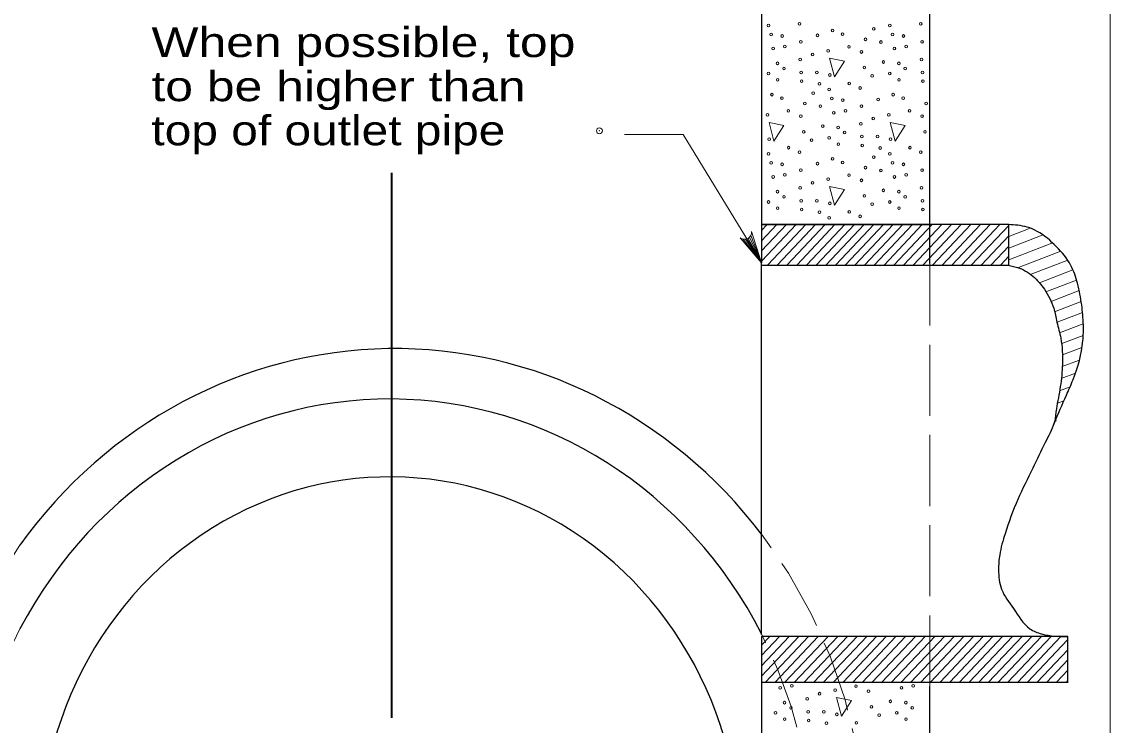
# Model space of a CAD drawing. Extents: x 1083.1 to 1117.1, y 697.4 to 719.4.
# Drawn here: x 1087.12 to 1092.81, y 703.92 to 707.6 of the extents above; entities that cross this region are included whole.
import ezdxf

# ---------------------------------------------------------------- set-up
doc = ezdxf.new("R2010")
doc.units = 0
doc.header["$LTSCALE"] = 0.062
doc.header["$PDMODE"] = 32
doc.header["$PDSIZE"] = 0.031
doc.linetypes.add('LONG_DASHED', pattern=[7.5, 6, -1.5])
doc.layers.add('1', color=7, linetype='Continuous', lineweight=13)

msp = doc.modelspace()

# ---------------------------------------------------------------- linework, layer by layer
at = {"layer": '1', "lineweight": 25}
for p, q in [((1090.98767, 710.498), (1090.98767, 706.54908)), ((1091.86725, 706.529), (1091.86725, 710.48442)), ((1090.98767, 706.54908), (1090.98767, 706.33992)), ((1090.98767, 706.5395), (1091.86867, 706.5395)), ((1091.86867, 706.5395), (1090.98767, 706.5395)), ((1091.86725, 706.33625), (1091.86725, 706.529)), ((1092.28083, 706.5395), (1091.86867, 706.5395)), ((1090.98767, 704.39392), (1090.98767, 706.33992)), ((1092.59017, 704.3835), (1090.987, 704.3835)), ((1090.98767, 704.3835), (1090.98767, 704.14825)), ((1092.59017, 704.14433), (1092.59017, 704.3835)), ((1090.98767, 704.14825), (1090.98767, 701.31858)), ((1090.98767, 704.14433), (1092.5915, 704.14433)), ((1091.86725, 700.32092), (1091.86725, 704.12275))]:
    msp.add_line(p, q, dxfattribs=at)
at = {"layer": '1'}
for p, q in [((1092.8115, 701.31858), (1092.8115, 707.72683)), ((1090.98767, 706.34775), (1091.16875, 706.5395)), ((1090.98767, 706.4015), (1091.118, 706.5395)), ((1090.98767, 706.45525), (1091.06725, 706.5395)), ((1090.98767, 706.50892), (1091.01642, 706.5395)), ((1091.02083, 706.32917), (1091.21942, 706.5395)), ((1091.07167, 706.32917), (1091.27017, 706.5395)), ((1091.12242, 706.32917), (1091.321, 706.5395)), ((1091.17308, 706.32917), (1091.37175, 706.5395)), ((1091.22383, 706.32917), (1091.4225, 706.5395)), ((1091.27458, 706.32917), (1091.47325, 706.5395)), ((1091.32542, 706.32917), (1091.524, 706.5395)), ((1091.37617, 706.32917), (1091.57475, 706.5395)), ((1091.42683, 706.32917), (1091.6255, 706.5395)), ((1091.47758, 706.32917), (1091.67625, 706.5395)), ((1091.52833, 706.32917), (1091.727, 706.5395)), ((1091.57917, 706.32917), (1091.77775, 706.5395)), ((1091.62992, 706.32917), (1091.8285, 706.5395)), ((1091.68067, 706.32917), (1091.87925, 706.5395)), ((1091.73133, 706.32917), (1091.93, 706.5395)), ((1091.78208, 706.32917), (1091.98075, 706.5395)), ((1091.83283, 706.32917), (1092.0315, 706.5395)), ((1091.88358, 706.32917), (1092.08225, 706.5395)), ((1091.93433, 706.32917), (1092.133, 706.5395)), ((1091.98508, 706.32917), (1092.18375, 706.5395)), ((1092.03583, 706.32917), (1092.2345, 706.5395)), ((1092.08658, 706.32917), (1092.28083, 706.53483)), ((1090.91675, 706.467), (1090.98767, 706.33992)), ((1090.92533, 706.47367), (1090.98767, 706.33992)), ((1090.93208, 706.48325), (1090.98767, 706.33992)), ((1092.13733, 706.32917), (1092.28083, 706.481)), ((1092.28083, 706.477), (1092.3935, 706.52042)), ((1092.28083, 706.41625), (1092.45508, 706.48342)), ((1090.892, 706.463), (1090.98767, 706.33992)), ((1090.9035, 706.46275), (1090.98767, 706.33992)), ((1092.18808, 706.32917), (1092.28083, 706.42733)), ((1092.28083, 706.35567), (1092.50575, 706.44233)), ((1092.23883, 706.32917), (1092.28083, 706.37358)), ((1092.33192, 706.31475), (1092.5525, 706.39975)), ((1092.39808, 706.27958), (1092.58942, 706.35325)), ((1092.44117, 706.2355), (1092.61575, 706.30283)), ((1092.47492, 706.18783), (1092.635, 706.2495)), ((1092.50283, 706.138), (1092.64875, 706.19408)), ((1092.52008, 706.08392), (1092.65925, 706.13758)), ((1092.53317, 706.02833), (1092.66642, 706.07967)), ((1092.54625, 705.97267), (1092.67058, 706.02067)), ((1092.55775, 705.9165), (1092.6705, 705.96)), ((1092.56208, 705.8575), (1092.66317, 705.89642)), ((1092.56058, 705.79633), (1092.64542, 705.829)), ((1092.55558, 705.73383), (1092.62975, 705.76233)), ((1092.54658, 705.66958), (1092.59625, 705.68883)), ((1092.53517, 705.6045), (1092.56842, 705.61742)), ((1092.52683, 705.51042), (1092.53092, 705.512)), ((1090.98767, 704.17658), (1091.183, 704.3835)), ((1090.98767, 704.23033), (1091.13233, 704.3835)), ((1090.98767, 704.28408), (1091.08158, 704.3835)), ((1090.98767, 704.33783), (1091.03083, 704.3835)), ((1091.00783, 704.14433), (1091.23383, 704.3835)), ((1091.05858, 704.14433), (1091.28458, 704.3835)), ((1091.10942, 704.14433), (1091.33533, 704.3835)), ((1091.16017, 704.14433), (1091.38608, 704.3835)), ((1091.21083, 704.14433), (1091.43683, 704.3835)), ((1091.26158, 704.14433), (1091.48758, 704.3835)), ((1091.31242, 704.14433), (1091.53833, 704.3835)), ((1091.36317, 704.14433), (1091.58908, 704.3835)), ((1091.41392, 704.14433), (1091.63983, 704.3835)), ((1091.46458, 704.14433), (1091.69058, 704.3835)), ((1091.51533, 704.14433), (1091.74133, 704.3835)), ((1091.56617, 704.14433), (1091.79208, 704.3835)), ((1091.61692, 704.14433), (1091.84275, 704.3835)), ((1091.66767, 704.14433), (1091.8935, 704.3835)), ((1091.71842, 704.14433), (1091.94425, 704.3835)), ((1091.76917, 704.14433), (1091.99508, 704.3835)), ((1091.81992, 704.14433), (1092.04583, 704.3835)), ((1091.87067, 704.14433), (1092.09658, 704.3835)), ((1091.9215, 704.14433), (1092.14725, 704.3835)), ((1091.97217, 704.14433), (1092.19808, 704.3835)), ((1092.02292, 704.14433), (1092.24883, 704.3835)), ((1092.07367, 704.14433), (1092.29958, 704.3835)), ((1092.12442, 704.14433), (1092.35033, 704.3835)), ((1092.17517, 704.14433), (1092.401, 704.3835)), ((1092.22592, 704.14433), (1092.45183, 704.3835)), ((1092.27667, 704.14433), (1092.50258, 704.3835)), ((1092.32742, 704.14433), (1092.55333, 704.3835)), ((1092.37817, 704.14433), (1092.59017, 704.36875)), ((1092.42892, 704.14433), (1092.59017, 704.315)), ((1092.47967, 704.14433), (1092.59017, 704.26133)), ((1092.53042, 704.14433), (1092.59017, 704.20758)), ((1092.58125, 704.14433), (1092.59017, 704.15375))]:
    msp.add_line(p, q, dxfattribs=at)
at = {"layer": '1', "lineweight": 35}
msp.add_line((1089.05217, 706.81108), (1089.05217, 703.95792), dxfattribs=at)
at = {"layer": '1', "linetype": 'LONG_DASHED'}
msp.add_line((1091.86725, 704.12275), (1091.86725, 706.33625), dxfattribs=at)
at = {"layer": '1'}
for points in [[(1091.34375, 707.40975), (1091.36942, 707.31242), (1091.42158, 707.39458)], [(1091.02658, 707.07392), (1091.05217, 706.97667), (1091.10442, 707.05883)], [(1091.66092, 707.07392), (1091.68658, 706.97667), (1091.73883, 707.05883)], [(1091.34375, 706.73817), (1091.36942, 706.64075), (1091.42158, 706.72292)], [(1091.38042, 704.06417), (1091.40608, 703.96683), (1091.45825, 704.049)]]:
    msp.add_lwpolyline(points, close=True, dxfattribs=at)
for points in [[(1090.98767, 706.33992), (1090.577, 707.011), (1090.27142, 707.011)], [(1090.87633, 706.47042), (1090.98767, 706.33992), (1090.93508, 706.50317)]]:
    msp.add_lwpolyline(points, dxfattribs=at)
at = {"layer": '1', "lineweight": 25}
msp.add_lwpolyline([(1090.98767, 706.32642), (1092.28083, 706.32642), (1092.28083, 706.5395)], dxfattribs=at)
at = {"layer": '1'}
msp.add_arc((1090.89909, 706.49869), 0.03631, 231.25375, 7.07988, dxfattribs=at)
for centre in [(1091.02402, 707.582), (1091.18589, 707.59017), (1091.35925, 707.55541), (1091.57447, 707.56387), (1091.65842, 707.582), (1091.8203, 707.59017), (1091.03776, 707.53487), (1091.09512, 707.52664), (1091.19277, 707.4958), (1091.28042, 707.53006), (1091.41148, 707.53638), (1091.53138, 707.50918), (1091.61216, 707.49497), (1091.67216, 707.53487), (1091.72952, 707.52664), (1091.82717, 707.4958), (1091.04797, 707.46049), (1091.10966, 707.4714), (1091.25467, 707.43026), (1091.33609, 707.44929), (1091.44484, 707.47017), (1091.50997, 707.44297), (1091.68237, 707.46049), (1091.74406, 707.4714), (1091.07117, 707.38342), (1091.18965, 707.40306), (1091.62474, 707.39041), (1091.70558, 707.38342), (1091.82405, 707.40306), (1091.02375, 707.32963), (1091.10485, 707.35683), (1091.19478, 707.33595), (1091.27704, 707.33595), (1091.34465, 707.32235), (1091.52541, 707.36136), (1091.56654, 707.31782), (1091.65815, 707.32963), (1091.73925, 707.35683), (1091.82918, 707.33595), (1091.07202, 707.29666), (1091.19731, 707.28972), (1091.29073, 707.27612), (1091.44658, 707.27791), (1091.70642, 707.29666), (1091.83172, 707.28972), (1091.04204, 707.21959), (1091.09428, 707.20056), (1091.25727, 707.22804), (1091.34122, 707.24618), (1091.35496, 707.19905), (1091.5031, 707.25435), (1091.67645, 707.21959), (1091.72868, 707.20056), (1091.21418, 707.17336), (1091.29496, 707.15914), (1091.41232, 707.19082), (1091.50997, 707.15998), (1091.59762, 707.19423), (1091.84858, 707.17336), (1091.01889, 707.11347), (1091.12764, 707.13435), (1091.19277, 707.10714), (1091.36517, 707.12466), (1091.42686, 707.13558), (1091.57188, 707.09444), (1091.65329, 707.11347), (1091.76204, 707.13435), (1091.82717, 707.10714), (1091.30754, 707.05459), (1091.38837, 707.04759), (1091.50685, 707.06724), (1091.02745, 706.98653), (1091.2082, 707.02554), (1091.24934, 706.98199), (1091.34095, 706.9938), (1091.42205, 707.021), (1091.51198, 707.00013), (1091.59424, 707.00013), (1091.66186, 706.98653), (1091.84261, 707.02554), (1091.12938, 706.94209), (1091.18589, 706.91852), (1091.38922, 706.96084), (1091.51452, 706.9539), (1091.60793, 706.9403), (1091.76378, 706.94209), (1091.8203, 706.91852), (1091.02402, 706.91035), (1091.03776, 706.86322), (1091.28042, 706.85841), (1091.35925, 706.88376), (1091.41148, 706.86473), (1091.57447, 706.89222), (1091.65842, 706.91035), (1091.67216, 706.86322), (1091.09512, 706.855), (1091.19277, 706.82416), (1091.53138, 706.83753), (1091.61216, 706.82332), (1091.72952, 706.855), (1091.82717, 706.82416), (1091.04797, 706.78884), (1091.10966, 706.79975), (1091.25467, 706.75861), (1091.33609, 706.77764), (1091.44484, 706.79852), (1091.50997, 706.77132), (1091.68237, 706.78884), (1091.74406, 706.79975), (1091.07117, 706.71177), (1091.18965, 706.73141), (1091.52541, 706.68971), (1091.62474, 706.71876), (1091.70558, 706.71177), (1091.82405, 706.73141), (1091.02375, 706.65798), (1091.10485, 706.68518), (1091.19478, 706.6643), (1091.27704, 706.6643), (1091.34465, 706.6507), (1091.56654, 706.64617), (1091.65815, 706.65798), (1091.73925, 706.68518), (1091.82918, 706.6643), (1091.07202, 706.62501), (1091.19731, 706.61807), (1091.29073, 706.60447), (1091.34122, 706.57453), (1091.44658, 706.60626), (1091.5031, 706.5827), (1091.70642, 706.62501), (1091.83172, 706.61807), (1091.14631, 704.12581), (1091.48148, 704.12458), (1091.78071, 704.12581), (1091.08461, 704.11489), (1091.29132, 704.08467), (1091.37274, 704.1037), (1091.54662, 704.09737), (1091.71902, 704.11489), (1091.10782, 704.03782), (1091.1415, 704.01124), (1091.2263, 704.05747), (1091.56205, 704.01577), (1091.66139, 704.04482), (1091.74222, 704.03782), (1091.7759, 704.01124), (1091.0604, 703.98403), (1091.23142, 703.99036), (1091.31369, 703.99036), (1091.3813, 703.97676), (1091.60318, 703.97222), (1091.6948, 703.98403), (1091.10867, 703.95107), (1091.23396, 703.94413), (1091.32738, 703.93053), (1091.48323, 703.93232), (1091.74307, 703.95107)]:
    msp.add_ellipse(centre, major_axis=(0, 0.00718), ratio=0.944544, dxfattribs=at)
at = {"layer": '1', "lineweight": 25}
for centre, major_axis, start_param, end_param in [((1089.06894, 703.28095), (0, -2.60983), 2.2495454, 4.0615652), ((1089.04094, 703.28499), (0, -2.34206), 2.0657148, 4.204739), ((1089.04277, 703.2802), (0, 1.93921), 4.5449685, 8.0045958)]:
    msp.add_ellipse(centre, major_axis=major_axis, ratio=0.944544, start_param=start_param, end_param=end_param, dxfattribs=at)
at = {"layer": '1', "linetype": 'LONG_DASHED'}
for centre, major_axis, start_param, end_param in [((1089.06894, 703.28095), (0, -2.60983), 4.0615652, 8.5327307), ((1089.04094, 703.28499), (0, -2.34206), 4.204739, 8.3489001)]:
    msp.add_ellipse(centre, major_axis=major_axis, ratio=0.944544, start_param=start_param, end_param=end_param, dxfattribs=at)
at = {"layer": '1', "lineweight": 25}
for points in [[(1092.5185, 705.501), (1092.582, 705.64633), (1092.61742, 705.72908), (1092.6685, 705.9315), (1092.67092, 706.01558), (1092.66225, 706.11942), (1092.64017, 706.23225), (1092.60583, 706.3255), (1092.53, 706.424), (1092.42975, 706.50408), (1092.37675, 706.5265), (1092.27958, 706.53967)], [(1092.27008, 706.32725), (1092.32625, 706.3155), (1092.407, 706.2695), (1092.46692, 706.20125), (1092.51592, 706.10158), (1092.533, 706.02917), (1092.55267, 705.94517), (1092.56142, 705.80983), (1092.55042, 705.69158), (1092.52975, 705.57458), (1092.5205, 705.50692)], [(1092.52058, 705.50708), (1092.5185, 705.501), (1092.47092, 705.3985), (1092.40633, 705.26442), (1092.32825, 705.1015), (1092.26117, 704.92133), (1092.23325, 704.81225), (1092.22717, 704.73342), (1092.24308, 704.631), (1092.30558, 704.52992), (1092.39117, 704.42475), (1092.45258, 704.39767), (1092.59017, 704.3835)]]:
    msp.add_spline(points, degree=3, dxfattribs=at)
at = {"layer": '1'}
msp.add_point((1090.1395, 707.03058), dxfattribs=at)

# ---------------------------------------------------------------- texts
for s, width, p in [('When possible, top', 1.25, (1087.79608, 707.41625)), ('to be higher than', 1.25, (1087.79608, 707.1855)), ('top of outlet pipe', 1.2, (1087.79608, 706.95475))]:
    msp.add_text(s, height=0.156, dxfattribs=dict(at, width=width)).set_placement(p)

doc.saveas('drawing.dxf')
